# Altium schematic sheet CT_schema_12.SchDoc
size 382 x 278 mm
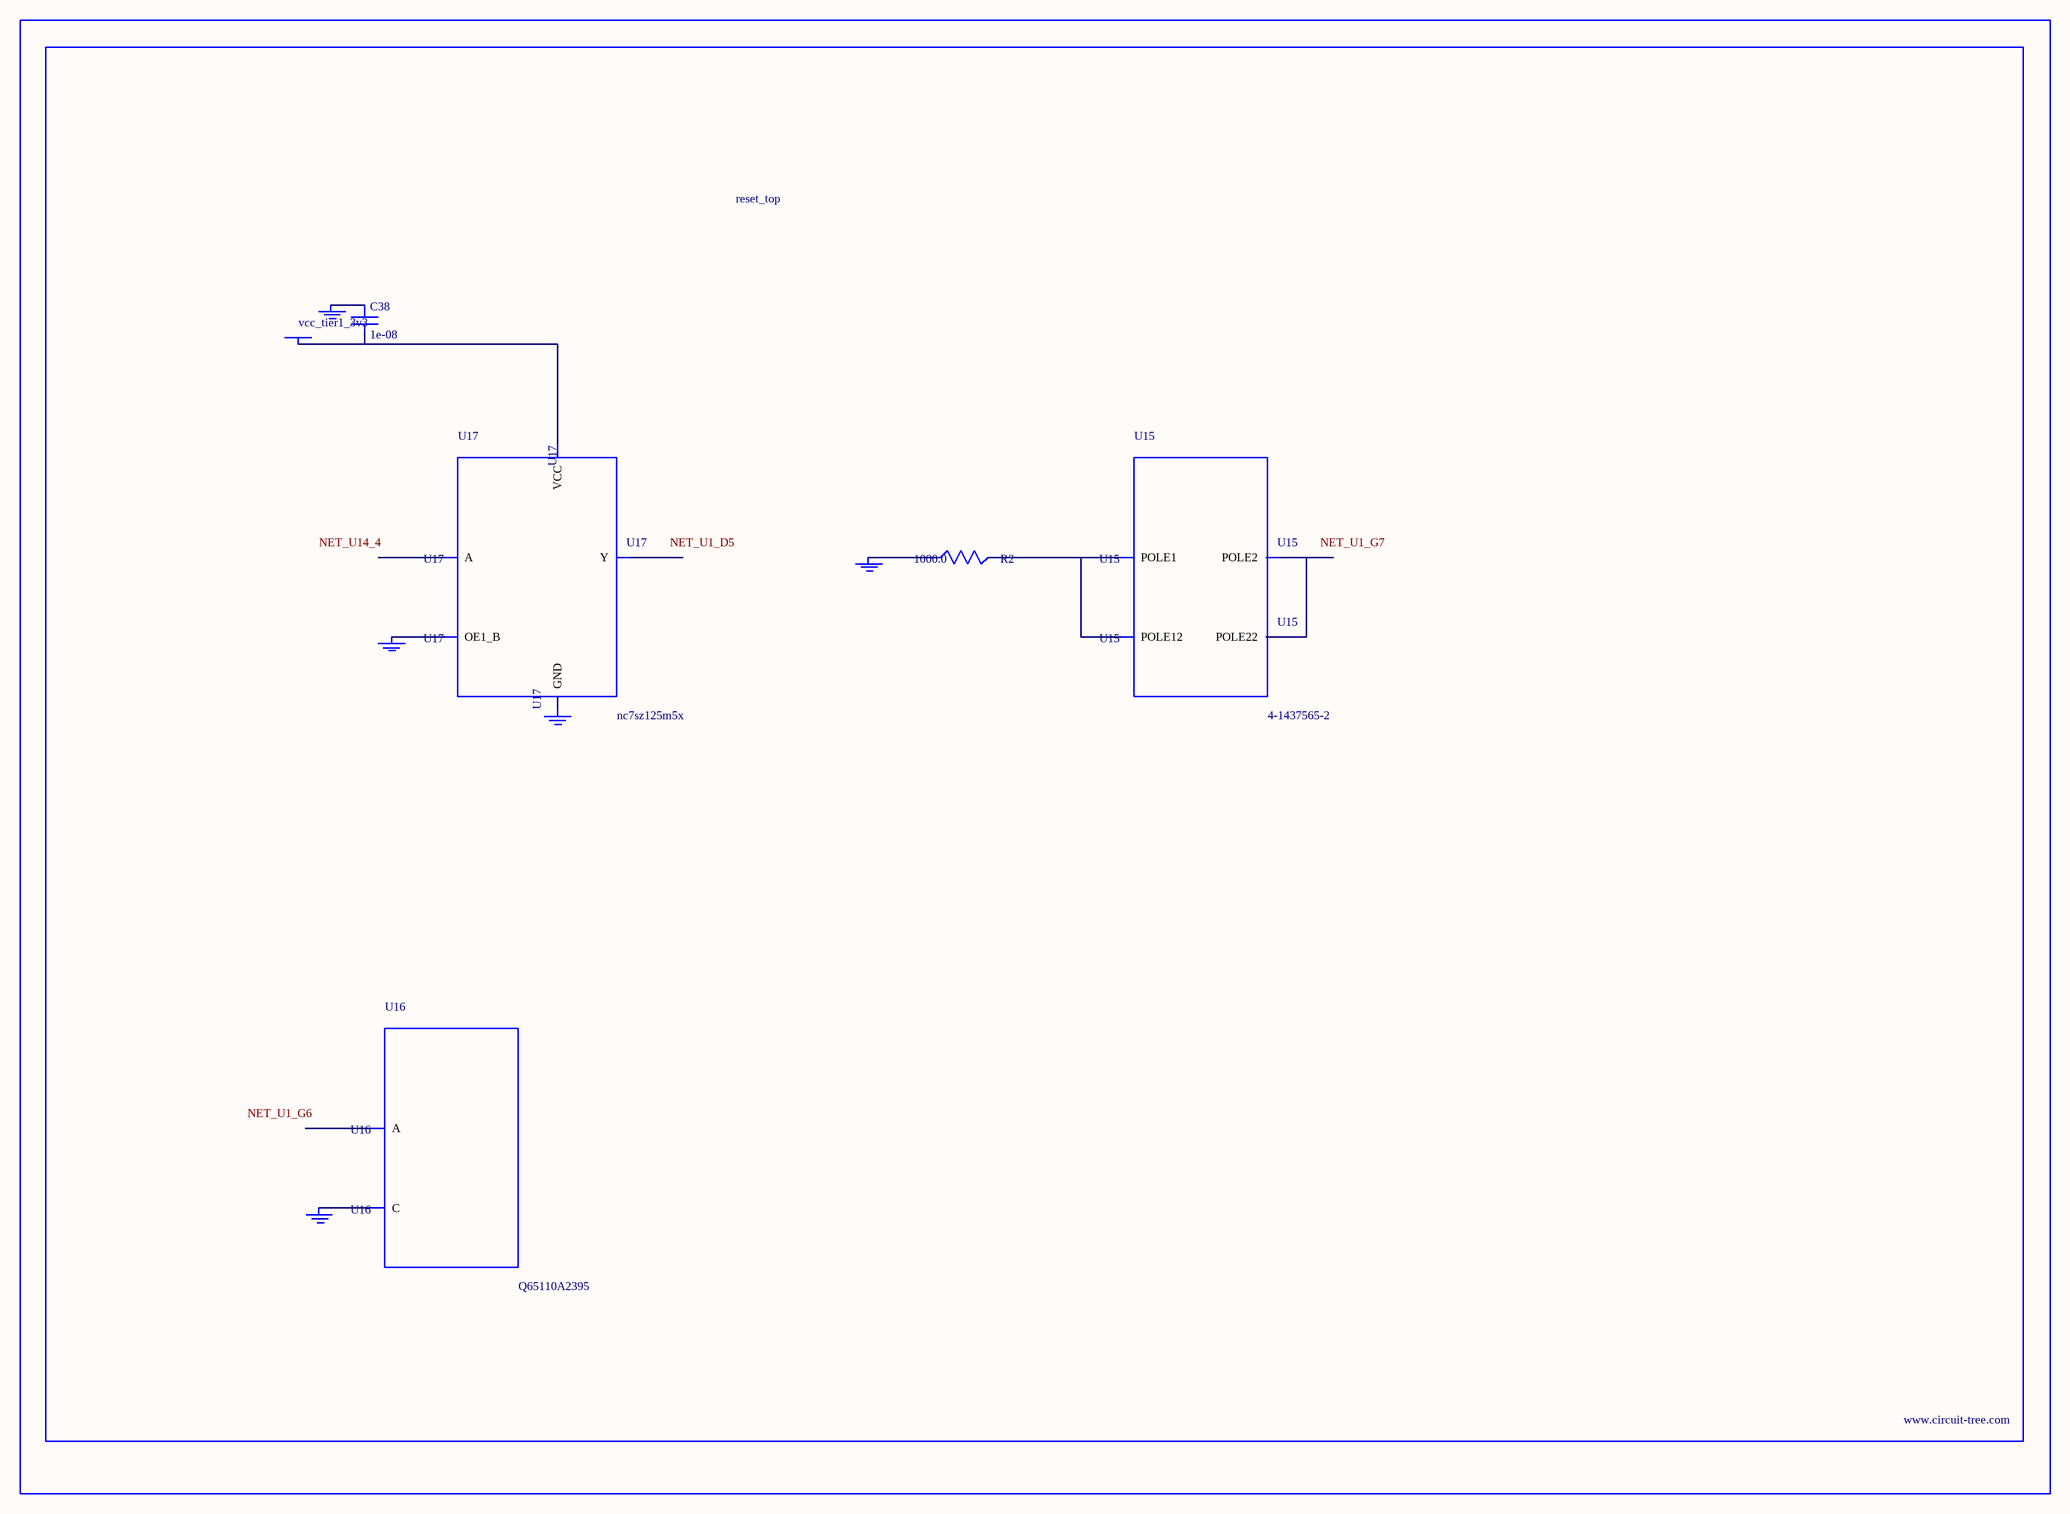
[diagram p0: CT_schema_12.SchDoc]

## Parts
BORDER11  (no value)
C38  1e-08  [C0402]
GND_INSTANCE_11_0  (no value)
GND_INSTANCE_11_1  (no value)
GND_INSTANCE_11_2  (no value)
GND_INSTANCE_11_3  (no value)
GND_INSTANCE_11_4  (no value)
POWER_INSTANCE_11_0  vcc_tier1_3v3
R2  1000.0  [R0603]
U15  4-1437565-2  [SW_4-1437565-2]
U16  Q65110A2395  [LGM67K-G1J2-24-Z]
U17  nc7sz125m5x  [NC7SZ125M5X]

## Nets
NetC38_1: C38.1 GND_INSTANCE_11_2.0(GND)
NetC38_2: C38.2 POWER_INSTANCE_11_0.0(PWR) U17.5(VCC)
NetGND_INSTANCE_11_0_0: GND_INSTANCE_11_0.0(GND) R2.1
NetGND_INSTANCE_11_1_0: GND_INSTANCE_11_1.0(GND) U16.C
NetGND_INSTANCE_11_3_0: GND_INSTANCE_11_3.0(GND) U17.1(OE1_B)
NetGND_INSTANCE_11_4_0: GND_INSTANCE_11_4.0(GND) U17.3(GND)
NetR2_2: R2.2 U15.1(POLE1) U15.2(POLE12)
NetU15_3: U15.3(POLE2) U15.4(POLE22)

Not connected (* = marked no-connect by the designer): U16 A; U17 2(A) 4(Y)

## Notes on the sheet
- Labels drawn without touching a wire or pin: NET_U1_D5, NET_U1_G6, NET_U1_G7, NET_U14_4

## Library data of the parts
BORDER11 = BORDER_PAGE11
C38 = C0402C103K3RAC
GND_INSTANCE_11_0-GND_INSTANCE_11_4 = GND
POWER_INSTANCE_11_0 = PWR
R2 = RC0603JR-071KL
